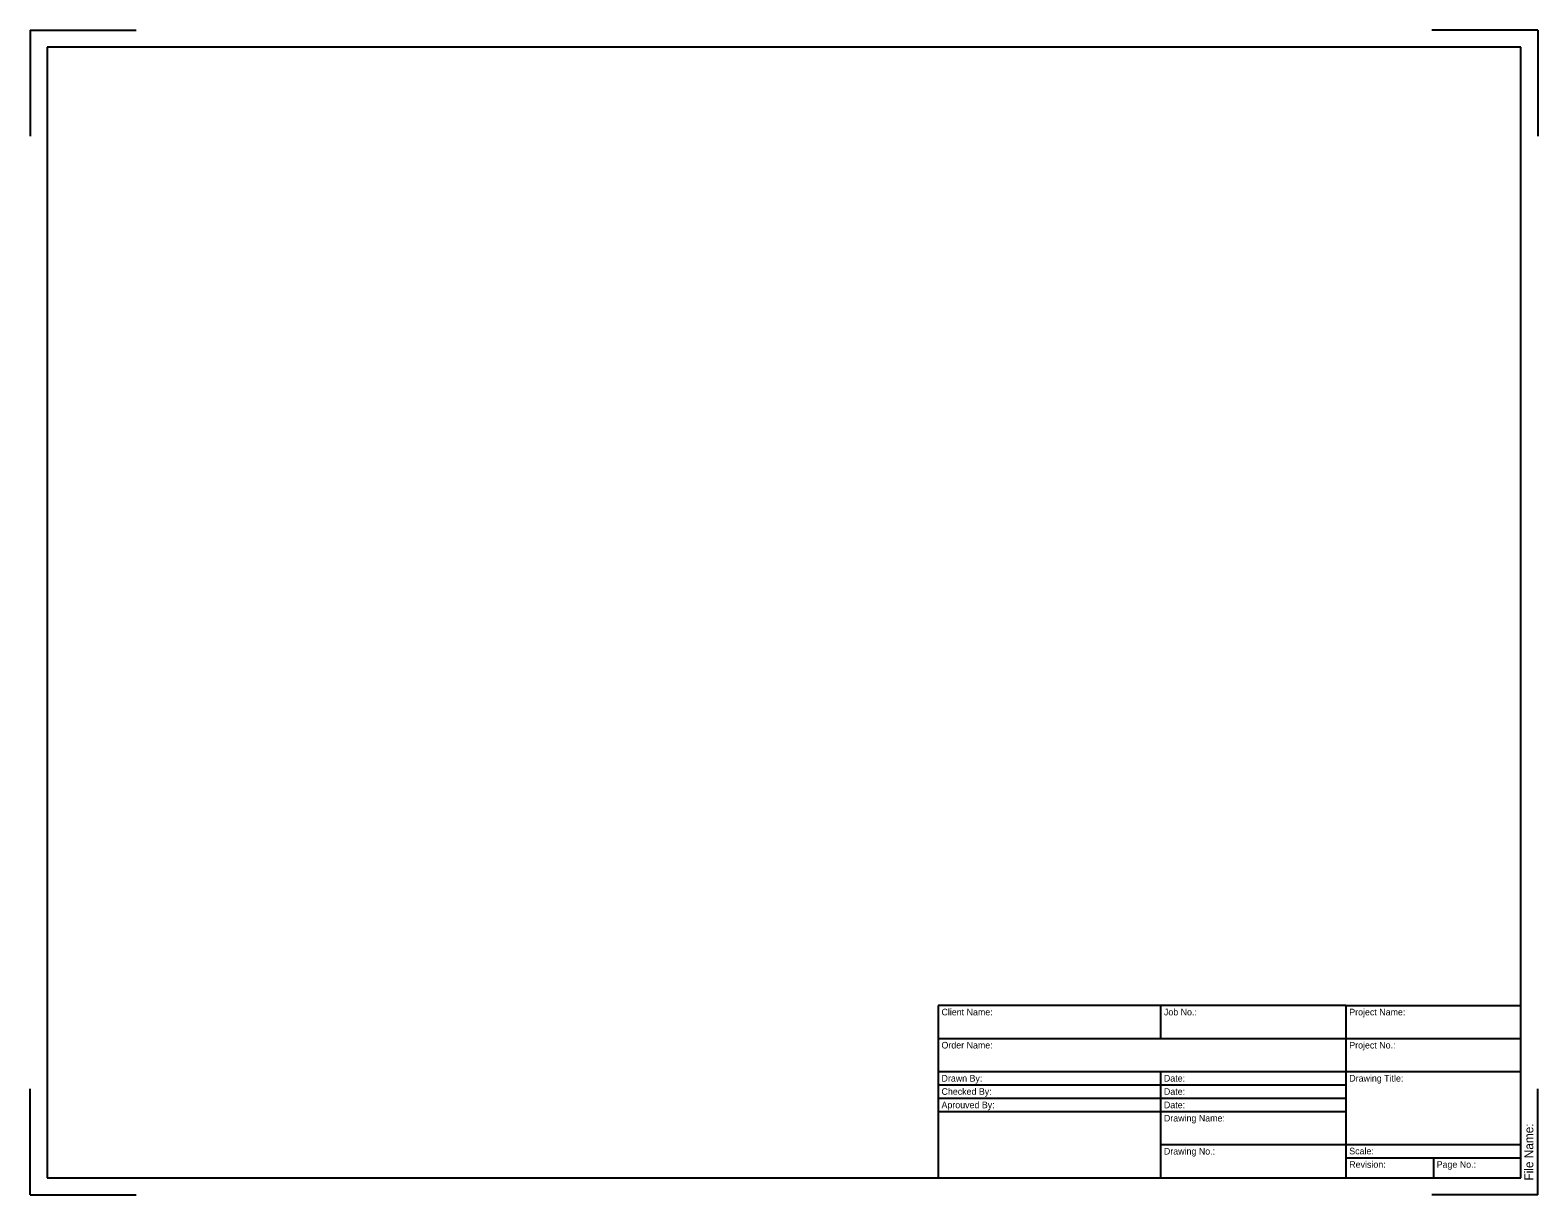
# Model space of a CAD drawing. Extents: x 0 to 88, y 0 to 68.
import ezdxf

# ---------------------------------------------------------------- set-up
doc = ezdxf.new("R2010")
doc.units = 0
doc.layers.add('STSF-BORDER', color=7, linetype='Continuous')

msp = doc.modelspace()

# ---------------------------------------------------------------- linework, layer by layer
at = {"layer": 'STSF-BORDER'}
for p, q in [((0, 68), (0, 61.818)), ((0, 68), (6.182, 68)), ((88, 68), (81.818, 68)), ((88, 68), (88, 61.818)), ((1, 67), (1, 1)), ((87, 67), (1, 67)), ((87, 1), (87, 67)), ((53, 11.056), (53, 1)), ((76.8, 11.056), (53, 11.056)), ((65.982, 11.056), (65.982, 9.125)), ((76.8, 11.056), (87, 11.056)), ((76.8, 11.056), (76.8, 1)), ((53, 9.125), (76.8, 9.125)), ((76.8, 9.125), (87, 9.125)), ((53, 7.193), (76.8, 7.193)), ((65.982, 7.193), (65.982, 1)), ((76.8, 7.193), (87, 7.193)), ((0, 0), (0, 6.182)), ((53, 6.42), (65.982, 6.42)), ((65.982, 6.42), (76.8, 6.42)), ((88, 0), (88, 6.182)), ((53, 5.647), (65.982, 5.647)), ((65.982, 5.647), (76.8, 5.647)), ((53, 4.864), (65.982, 4.864)), ((65.982, 4.864), (76.8, 4.864)), ((65.982, 2.932), (76.8, 2.932)), ((76.8, 2.943), (87, 2.943)), ((76.8, 2.17), (87, 2.17)), ((81.9, 2.17), (81.9, 1)), ((1, 1), (87, 1)), ((65.982, 1), (76.8, 1)), ((0, 0), (6.182, 0)), ((88, 0), (81.818, 0))]:
    msp.add_line(p, q, dxfattribs=at)

# ---------------------------------------------------------------- texts
for s, height, p in [('Client Name:', 0.38636, (53.193, 10.477)), ('Job No.:', 0.3864, (66.175, 10.477)), ('Project Name:', 0.38636, (76.993, 10.477)), ('Order Name:', 0.38636, (53.193, 8.545)), ('Project No.:', 0.38636, (76.993, 8.545)), ('Checked By:', 0.38636, (53.193, 5.84)), ('Drawn By:', 0.3864, (53.193, 6.613)), ('Date:', 0.3864, (66.175, 6.613)), ('Date:', 0.3864, (66.175, 5.84)), ('Drawing Title:', 0.38636, (76.993, 6.613)), ('Aprouved By:', 0.38636, (53.193, 5.057)), ('Date:', 0.3864, (66.175, 5.057)), ('Drawing Name:', 0.38636, (66.175, 4.284)), ('Drawing No.:', 0.38636, (66.175, 2.352)), ('Scale:', 0.3864, (76.993, 2.363)), ('Revision:', 0.3864, (76.993, 1.58)), ('Page No.:', 0.3864, (82.093, 1.58))]:
    msp.add_text(s, height=height, dxfattribs=at).set_placement(p)
msp.add_text('File Name:', height=0.5152, rotation=90, dxfattribs=at).set_placement((87.734, 0.837))

doc.saveas('drawing.dxf')
